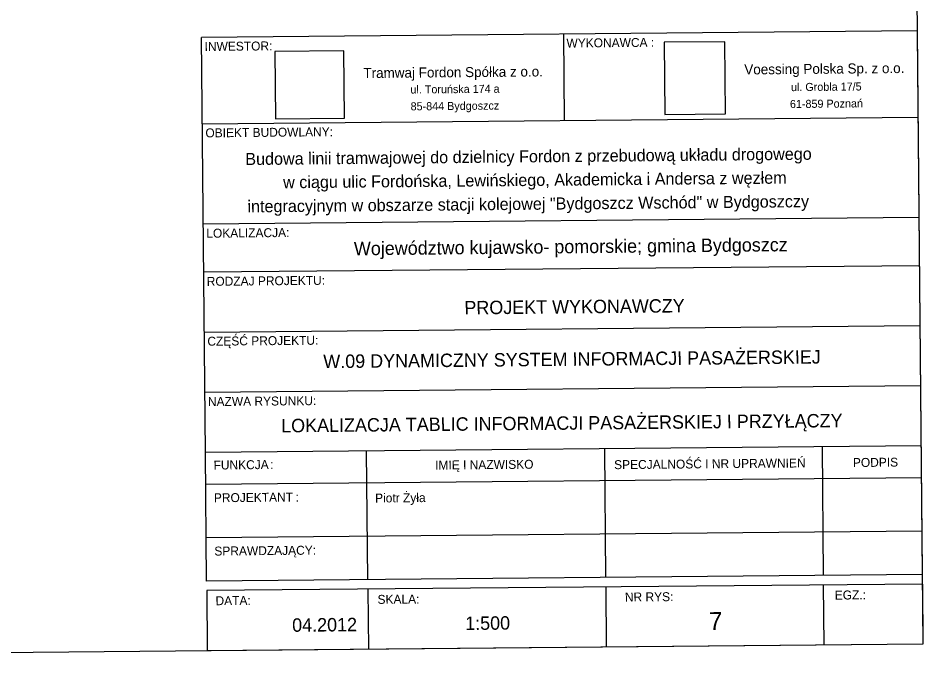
# Model space of a CAD drawing. Extents: x 6505045 to 6511721, y 5887996 to 5893535.
# Drawn here: x 6507860.2 to 6507961.4, y 5890166.7 to 5890238.6 of the extents above; entities that cross this region are included whole.
import ezdxf

# ---------------------------------------------------------------- set-up
doc = ezdxf.new("R2010")
doc.units = 0
for name, color, linetype in [('__legenda', 7, 'Continuous'), ('Default', 7, 'Continuous'), ('P_tabela', 7, 'Continuous'), ('SA_Linie-020', 7, 'Continuous'), ('SA_Stempel_Text-020', 7, 'Continuous'), ('SA_Stempel_Text-030', 7, 'Continuous'), ('SA_Stempel_Text-035', 7, 'Continuous'), ('SA_Unterschrift_Text', 7, 'Continuous')]:
    doc.layers.add(name, color=color, linetype=linetype)

msp = doc.modelspace()

# ---------------------------------------------------------------- linework, layer by layer
at = {"layer": '__legenda'}
msp.add_lwpolyline([(6507932.5, 5890227.82), (6507939.3, 5890227.88), (6507939.23, 5890235.95), (6507932.43, 5890235.89)], close=True, dxfattribs=at)
at = {"layer": 'Default'}
msp.add_lwpolyline([(6507888.98, 5890227.35), (6507896.71, 5890227.42), (6507896.64, 5890234.95), (6507888.91, 5890234.88)], close=True, dxfattribs=at)
at = {"layer": 'P_tabela'}
for p, q in [((6507960.06, 5890308.06), (6507961.36, 5890168.61)), ((6507960.06, 5890308.06), (6507961.36, 5890168.61)), ((6507960.06, 5890308.06), (6507961.36, 5890168.61)), ((6507961.36, 5890168.61), (6507760.38, 5890166.74)), ((6507961.36, 5890168.61), (6507760.38, 5890166.74)), ((6507961.36, 5890168.61), (6507760.38, 5890166.74))]:
    msp.add_line(p, q, dxfattribs=at)
at = {"layer": 'SA_Linie-020'}
for p, q in [((6507960.72, 5890237.18), (6507880.72, 5890236.44)), ((6507881.16, 5890190.02), (6507880.72, 5890236.44)), ((6507921.17, 5890236.81), (6507921.26, 5890227.16)), ((6507960.72, 5890237.18), (6507961.29, 5890176.39)), ((6507880.81, 5890226.78), (6507960.81, 5890227.52)), ((6507960.92, 5890216.3), (6507880.92, 5890215.55)), ((6507960.97, 5890210.92), (6507880.97, 5890210.18)), ((6507961.03, 5890204.2), (6507881.03, 5890203.46)), ((6507961.03, 5890204.2), (6507881.03, 5890203.46)), ((6507961.09, 5890197.49), (6507881.09, 5890196.74)), ((6507961.15, 5890190.77), (6507881.16, 5890190.02)), ((6507881.29, 5890175.65), (6507881.16, 5890190.02)), ((6507899.31, 5890175.81), (6507899.18, 5890190.19)), ((6507925.75, 5890190.44), (6507925.89, 5890176.06)), ((6507950.09, 5890190.66), (6507950.22, 5890176.29)), ((6507961.19, 5890187.21), (6507881.19, 5890186.46)), ((6507961.24, 5890181.25), (6507881.25, 5890180.5)), ((6507961.29, 5890176.39), (6507881.29, 5890175.65)), ((6507961.3, 5890175.33), (6507881.3, 5890174.59)), ((6507881.3, 5890174.59), (6507881.36, 5890167.87)), ((6507899.32, 5890174.75), (6507899.39, 5890168.03)), ((6507925.9, 5890175), (6507925.96, 5890168.28)), ((6507950.23, 5890175.23), (6507950.3, 5890168.51)), ((6507961.3, 5890175.33), (6507961.36, 5890168.61)), ((6507961.36, 5890168.61), (6507881.36, 5890167.87))]:
    msp.add_line(p, q, dxfattribs=at)

# ---------------------------------------------------------------- texts
at = {"layer": 'SA_Stempel_Text-020'}
for s, p in [('WYKONAWCA :', (6507921.52, 5890235.3)), ('INWESTOR:', (6507881.07, 5890234.92)), ('OBIEKT BUDOWLANY:', (6507881.16, 5890225.26)), ('LOKALIZACJA:', (6507881.26, 5890214.04)), ('RODZAJ PROJEKTU:', (6507881.31, 5890208.66)), ('CZĘŚĆ PROJEKTU:', (6507881.38, 5890201.97)), ('NAZWA RYSUNKU:', (6507881.44, 5890195.22)), ('FUNKCJA', (6507882.07, 5890188.13)), (':', (6507888.4, 5890188.19)), ('IMIĘ I NAZWISKO', (6507906.84, 5890188.12)), ('SPECJALNOŚĆ I NR UPRAWNIEŃ', (6507926.85, 5890188.17)), ('PODPIS', (6507953.54, 5890188.41)), ('PROJEKTANT', (6507882.11, 5890184.47)), (':', (6507891.24, 5890184.55)), ('SPRAWDZAJĄCY:', (6507882.16, 5890178.51)), ('EGZ.:', (6507951.51, 5890173.59)), ('DATA:', (6507882.29, 5890172.96)), ('SKALA:', (6507900.4, 5890173.11)), ('NR RYS:', (6507928.05, 5890173.37))]:
    msp.add_text(s, height=1, rotation=0.535, dxfattribs=at).set_placement(p)
at = {"layer": 'SA_Stempel_Text-030'}
for s, height, p in [('04.2012', 1.5, (6507890.86, 5890169.99)), ('1:500', 1.5, (6507910.2, 5890170.19)), ('7', 2, (6507937.46, 5890170.18))]:
    msp.add_text(s, height=height, rotation=0.535, dxfattribs=at).set_placement(p)
at = {"layer": 'SA_Stempel_Text-035'}
for s, height, p in [('Budowa linii tramwajowej do dzielnicy Fordon z przebudową układu drogowego', 1.35, (6507885.62, 5890222.17)), ('w ciągu ulic Fordońska, Lewińskiego, Akademicka i Andersa z węzłem', 1.35, (6507889.85, 5890219.57)), ('integracyjnym w obszarze stacji kolejowej "Bydgoszcz Wschód" w Bydgoszczy', 1.35, (6507885.86, 5890216.87)), ('Województwo kujawsko- pomorskie; gmina Bydgoszcz', 1.5, (6507897.76, 5890212.08)), ('PROJEKT WYKONAWCZY', 1.5, (6507910.11, 5890205.47)), ('W.09 DYNAMICZNY SYSTEM INFORMACJI PASAŻERSKIEJ', 1.5, (6507894.34, 5890199.46)), ('LOKALIZACJA TABLIC INFORMACJI PASAŻERSKIEJ I PRZYŁĄCZY', 1.5, (6507889.63, 5890192.28))]:
    msp.add_text(s, height=height, rotation=0.535, dxfattribs=at).set_placement(p)
at = {"layer": 'SA_Unterschrift_Text'}
for s, height, p in [('Tramwaj Fordon Spółka z o.o.', 1.125, (6507898.82, 5890231.89)), ('Voessing Polska Sp. z o.o.', 1.125, (6507941.4, 5890232.29)), ('ul. Toruńska 174 a', 0.9, (6507904.08, 5890230.16)), ('ul. Grobla 17/5', 0.9, (6507946.62, 5890230.43)), ('85-844 Bydgoszcz', 0.9, (6507904.1, 5890228.28)), ('61-859 Poznań', 0.9, (6507946.5, 5890228.54)), ('Piotr Żyła', 1, (6507900.13, 5890184.44))]:
    msp.add_text(s, height=height, rotation=0.535, dxfattribs=at).set_placement(p)

doc.saveas('drawing.dxf')
